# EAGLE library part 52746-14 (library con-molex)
FPC Connector ZIF for SMT 0.5mm Source: http://www.farnell.com/datasheets/73044.pdf [DWG. NO. (Sheet 1 OF 2) SD-52746-**17]
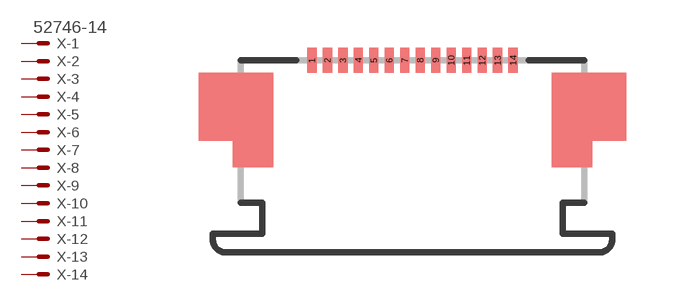
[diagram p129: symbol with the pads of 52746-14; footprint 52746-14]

Designator prefix X; gates -1=MV -2=M -3=M -4=M -5=M -6=M -7=M -8=M -9=M -10=M -11=M -12=M -13=M -14=M

## 52746-14 (OC_FARNELL: unknown; OC_NEWARK: unknown)  [52746-14]
1  -1:S  pas
2  -2:S  pas
3  -3:S  pas
4  -4:S  pas
5  -5:S  pas
6  -6:S  pas
7  -7:S  pas
8  -8:S  pas
9  -9:S  pas
10  -10:S  pas
11  -11:S  pas
12  -12:S  pas
13  -13:S  pas
14  -14:S  pas

## Footprint 52746-14 (pad centres in mm)
FPC Connector ZIF for SMT 0.5mm Source: http://www.farnell.com/datasheets/73044.pdf [DWG. NO. (Sheet 1 OF 2) SD-52746-**17]
smd 0.3 x 0.8: 1 -3.25,0.6; 2 -2.75,0.6; 3 -2.25,0.6; 4 -1.75,0.6; 5 -1.25,0.6; 6 -0.75,0.6; 7 -0.25,0.6; 8 0.25,0.6; 9 0.75,0.6; 10 1.25,0.6; 11 1.75,0.6; 12 2.25,0.6; 13 2.75,0.6; 14 3.25,0.6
